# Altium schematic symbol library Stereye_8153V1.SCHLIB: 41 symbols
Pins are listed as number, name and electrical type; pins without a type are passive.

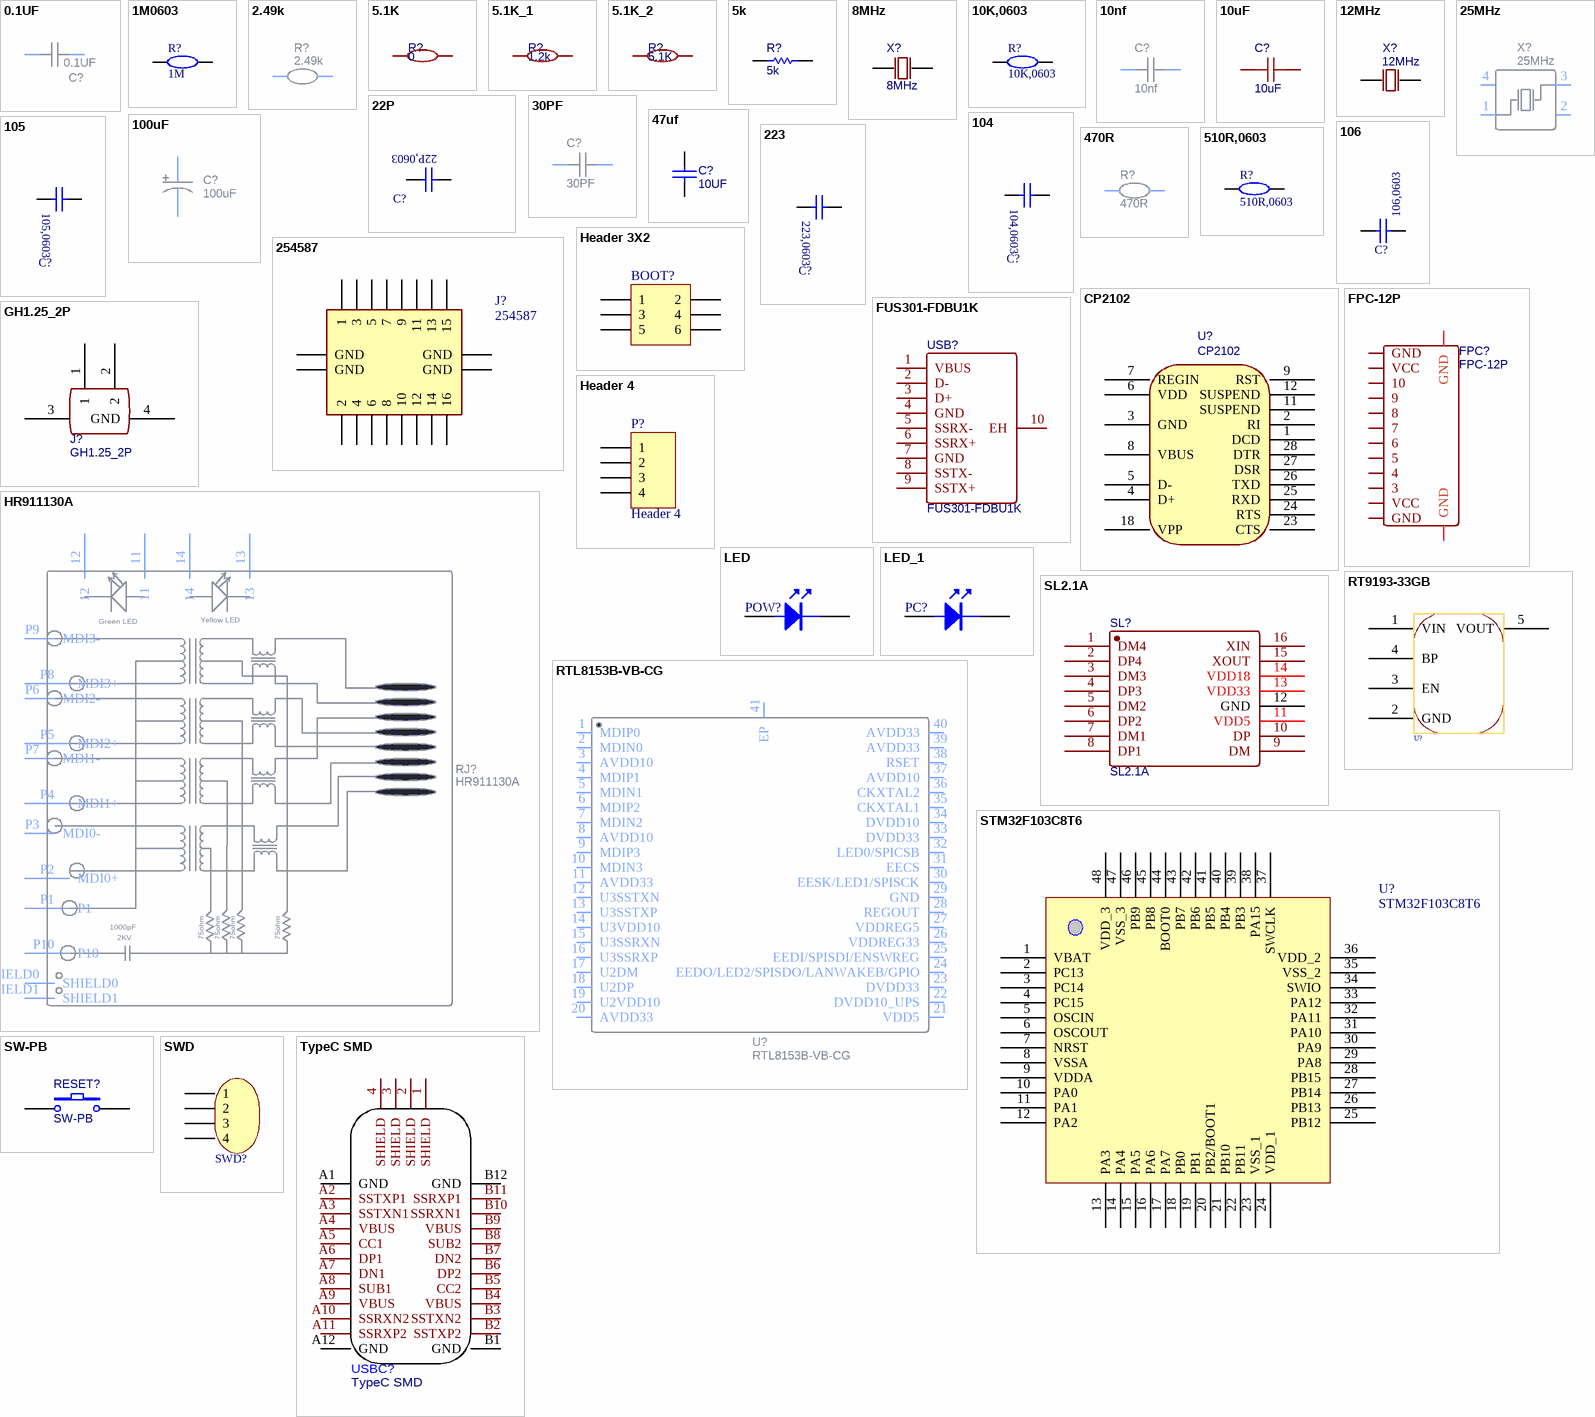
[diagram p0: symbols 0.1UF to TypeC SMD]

## 0.1UF
designator C?
nameAlias: Value(F); Contributor: LCEDA_Lib
footprint C0402_NEW
pins: 1, 2

## 1M0603
designator R?, comment 1M
BOM_Manufacturer: Uniroyal Elec; BOM_Manufacturer Part: 0603WAF1054T5E
footprint 6-0805_N (Chip Resistor, Body 2.0x1.2mm, IPC Medium Density)
pins: 1, 2

## 2.49k
designator R?
nameAlias: Value(Ω); Contributor: LCEDA_Lib
footprint R0603_NEW
pins: 1, 2

## 5.1K
designator R?, comment 0
BOM_Manufacturer: Tyohm; BOM_Manufacturer Part: RMC04025.1K1%N; nameAlias: Resistance (Ohms); Contributor: LCSC
footprint 6-0805_L (Chip Resistor, Body 2.0x1.2mm, IPC High Density)
pins: 1, 2

## 5.1K_1
designator R?, comment 1.2k
BOM_Manufacturer: Tyohm; BOM_Manufacturer Part: RMC04025.1K1%N; nameAlias: Resistance (Ohms); Contributor: LCSC
footprint 6-0805_L (Chip Resistor, Body 2.0x1.2mm, IPC High Density)
pins: 1, 2

## 5.1K_2
designator R?, comment 5.1K
BOM_Manufacturer: Tyohm; BOM_Manufacturer Part: RMC04025.1K1%N; nameAlias: Resistance (Ohms); Contributor: LCSC
footprint 6-0805_L (Chip Resistor, Body 2.0x1.2mm, IPC High Density)
pins: 1, 2

## 5k
designator R?
catid: 20; sourceId: RoYWUgdzx
footprint C0402_NEW
pins: 1, 2

## 8MHz
designator X?
BOM_Manufacturer: ZheJiang East Crystal Elec; BOM_Manufacturer Part: B08000J065; nameAlias: Frequency; Contributor: LCSC
footprint XTAL
pins: 1 OSC1, 2 OSC2

## 10K,0603
designator R?
BOM_Manufacturer: UniOhm; BOM_Manufacturer Part: 060300J0103T5E
footprint C0402_NEW
pins: 1, 2

## 10nf
designator C?
nameAlias: Value(F); Contributor: LCEDA_Lib
footprint C0402_NEW
pins: 1, 2

## 10uF
designator C?
BOM_Manufacturer: SAMSUNG; BOM_Manufacturer Part: CL10A106MP8NNNC; nameAlias: Capacitance
footprint C0402_NEW
pins: 1, 2

## 12MHz
designator X?
BOM_Manufacturer: YXC; BOM_Manufacturer Part: X49SD12MSD2SC; nameAlias: Frequency
footprint XTAL
pins: 1 OSC1, 2 OSC2

## 22P
designator C?  (value not drawn)
BOM_Manufacturer: YAGEO; BOM_Manufacturer Part: CC0603KRX7R9BB104
footprint C0402_NEW
pins: 1, 2

## 25MHz
designator X?
BOM_Manufacturer: Zhejiang Abel Elec; BOM_Manufacturer Part: SMD-3225_4P25MHZ12PF10PPM-40~+85℃; nameAlias: Frequency; Contributor: LCSC; SMT Type: Extend
footprint OSC-SMD_4P-L3.2-W2.5-BL
footprint OSC-SMD_4P-L3.2-W2.5-BL
pins: 1 OSC1, 2 GND, 3 OSC2, 4 GND

## 30PF
designator C?
nameAlias: Value(F); Contributor: LCEDA_Lib
footprint C0402_NEW
pins: 1, 2

## 47uf
designator C?, comment 10UF
catid: 20; sourceId: aYgasJ1jB
footprint C0402_NEW
pins: 1, 2

## 100uF
designator C?
BOM_Manufacturer: SamYoung Electronics; BOM_Manufacturer Part: MVK16VC100M6.3*5_6.3TP; nameAlias: Capacitance; Contributor: LCSC
footprint CAP-SMD_BD6.3-L6.6-W6.6-FD
pins: 1, 2

## 104
designator C?  (value not drawn)
BOM_Manufacturer: YAGEO; BOM_Manufacturer Part: CC0603KRX7R9BB104
footprint C0402_NEW
pins: 1, 2

## 105
designator C?  (value not drawn)
BOM_Manufacturer: YAGEO; BOM_Manufacturer Part: CC0603KRX7R9BB104
footprint C0402_NEW
pins: 1, 2

## 106
designator C?  (value not drawn)
BOM_Manufacturer: YAGEO; BOM_Manufacturer Part: CC0603KRX7R9BB104
footprint C0402_NEW
pins: 1, 2

## 223
designator C?  (value not drawn)
BOM_Manufacturer: YAGEO; BOM_Manufacturer Part: CC0603KRX7R9BB104
footprint C0402_NEW
pins: 1, 2

## 470R
designator R?
nameAlias: Value(Ω); Contributor: LCEDA_Lib
footprint C0402_NEW
pins: 1, 2

## 510R,0603
designator R?
BOM_Manufacturer: UniOhm; BOM_Manufacturer Part: 0603WAJ0511T5E
footprint C0402_NEW
pins: 1, 2

## 254587
designator J?
Connector; Manufacturer_Name: ERNI
footprint MH-16
pins: A1 16, A2 14, A3 12, A4 10, A5 8, A6 6, A7 4, A8 2, B1 15, B2 13, B3 11, B4 9, B5 7, B6 5, B7 3, B8 1, MP1 GND, MP2 GND, MP3 GND, MP4 GND

## CP2102
designator U?
catid: 20; sourceId: 1y8642nlj
footprint QFN28G_0.5-5X5MM
footprint CP2102-28G
pins: 1 DCD, 2 RI, 3 GND, 4 D+, 5 D-, 6 VDD, 7 REGIN, 8 VBUS, 9 RST, 11 SUSPEND, 12 SUSPEND, 18 VPP, 23 CTS, 24 RTS, 25 RXD, 26 TXD, 27 DSR, 28 DTR

## FPC-12P
designator FPC?
BOM_Manufacturer: JUSHUO; BOM_Manufacturer Part: AFC01-S12FCA-00; Contributor: zhqtl2002
footprint FPC-0.5MM-12P
pins: 1 GND, 2 VCC, 3, 4, 5, 6, 7, 8, 9, 10, 11 VCC, 12 GND, 13 GND, 14 GND

## FUS301-FDBU1K
designator USB?
BOM_Manufacturer: TXGA; Contributor: LCSC
footprint USB3.0-A-TH_FUS301-FDBU1K
pins: 1 VBUS, 2 D-, 3 D+, 4 GND, 5 SSRX-, 6 SSRX+, 7 GND, 8 SSTX-, 9 SSTX+, 10 EH

## GH1.25_2P
designator J?
Contributor: AKER
footprint GH1.25_2P
pins: 1, 2, 3, 4 GND

## Header 3X2
designator BOOT?  (value not drawn)
Header, 3-Pin, Dual row
signal-integrity model Connector
footprint HDR2X3 (Connector; Header; 3x2 Position)
pins: 1, 2, 3, 4, 5, 6

## Header 4
designator P?
Header, 4-Pin
footprint HDR1X4 (Connector; Header; 4 Position)
signal-integrity model Connector
pins: 1, 2, 3, 4

## HR911130A
designator RJ?
BOM_Manufacturer: HANRUN
footprint RJ45-TH_HR911130A
pins: 11, 12, 13, 14, P1, P2 MDI0+, P3 MDI0-, P4 MDI1+, P5 MDI2+, P6 MDI2-, P7 MDI1-, P8 MDI3+, P9 MDI3-, P10, SHIELD0, SHIELD1

## LED
designator POW?, comment LEDred  (value not drawn)
footprint LED; pin to pad A>1 K>2
pins: A 1, K 2

## LED_1
designator PC?, comment LEDgreen  (value not drawn)
footprint LED; pin to pad A>1 K>2
pins: A 1, K 2

## RT9193-33GB
designator U?  (value not drawn)
ICA_MFR_NAME: RICHTEK; ICA_PARTNUM: $$2191094$$RT9193-15CU5; Part Number: TMP-13
footprint SOT-23-5
pins: 1 VIN, 2 GND, 3 EN, 4 BP, 5 VOUT

## RTL8153B-VB-CG
designator U?
BOM_Manufacturer: REALTEK(瑞昱); Contributor: LCSC
footprint QFN-40_L5.0-W5.0-P0.40-BL-EP3.7
pins: 1 MDIP0, 2 MDIN0, 3 AVDD10, 4 MDIP1, 5 MDIN1, 6 MDIP2, 7 MDIN2, 8 AVDD10, 9 MDIP3, 10 MDIN3, 11 AVDD33, 12 U3SSTXN, 13 U3SSTXP, 14 U3VDD10, 15 U3SSRXN, 16 U3SSRXP, 17 U2DM, 18 U2DP, 19 U2VDD10, 20 AVDD33, 21 VDD5, 22 DVDD10_UPS, 23 DVDD33, 24 EEDO/LED2/SPISDO/LANWAKEB/GPIO, 25 EEDI/SPISDI/ENSWREG, 26 VDDREG33, 27 VDDREG5, 28 REGOUT, 29 GND, 30 EESK/LED1/SPISCK, 31 EECS, 32 LED0/SPICSB, 33 DVDD33, 34 DVDD10, 35 CKXTAL1, 36 CKXTAL2, 37 AVDD10, 38 RSET, 39 AVDD33, 40 AVDD33, 41 EP

## SL2.1A
designator SL?
BOM_Manufacturer: CoreChips; Contributor: LCSC; SMT Type: Extend
footprint SOP-16_L10.0-W3.9-P1.27-LS6.0-BL
pins: 1 DM4, 2 DP4, 3 DM3, 4 DP3, 5 DM2, 6 DP2, 7 DM1, 8 DP1, 9 DM, 10 DP, 11 VDD5, 12 GND, 13 VDD33, 14 VDD18, 15 XOUT, 16 XIN

## STM32F103C8T6
designator U?
footprint STM32-48P
pins: 1 VBAT, 2 PC13, 3 PC14, 4 PC15, 5 OSCIN, 6 OSCOUT, 7 NRST, 8 VSSA, 9 VDDA, 10 PA0, 11 PA1, 12 PA2, 13 PA3, 14 PA4, 15 PA5, 16 PA6, 17 PA7, 18 PB0, 19 PB1, 20 PB2/BOOT1, 21 PB10, 22 PB11, 23 VSS_1, 24 VDD_1, 25 PB12, 26 PB13, 27 PB14, 28 PB15, 29 PA8, 30 PA9, 31 PA10, 32 PA11, 33 PA12, 34 SWIO, 35 VSS_2, 36 VDD_2, 37 SWCLK, 38 PA15, 39 PB3, 40 PB4, 41 PB5, 42 PB6, 43 PB7, 44 BOOT0, 45 PB8, 46 PB9, 47 VSS_3, 48 VDD_3

## SW-PB
designator RESET?
Contributor: liujiayu6388
footprint 贴片按键（红头）
footprint Key
pins: 1, 2

## SWD
designator SWD?  (value not drawn)
BOM_Manufacturer: Ckmtw; BOM_Manufacturer Part: 210S-1*4P L=11.6MMGold-plated black
footprint HDR1X4H (Connector; Header; 4 Position; Right Angle)
pins: 1, 2, 3, 4

## TypeC SMD
designator USBC?
footprint USB-C-SMD_MC-312D-C
pins: 1 SHIELD, 2 SHIELD, 3 SHIELD, 4 SHIELD, A1 GND, A2 SSTXP1, A3 SSTXN1, A4 VBUS, A5 CC1, A6 DP1, A7 DN1, A8 SUB1, A9 VBUS, A10 SSRXN2, A11 SSRXP2, A12 GND, B1 GND, B2 SSTXP2, B3 SSTXN2, B4 VBUS, B5 CC2, B6 DP2, B7 DN2, B8 SUB2, B9 VBUS, B10 SSRXN1, B11 SSRXP1, B12 GND

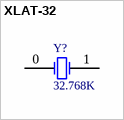
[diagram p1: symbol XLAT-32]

## XLAT-32
designator Y?, comment 32.768K
BOM_Manufacturer: KDS; BOM_Manufacturer Part: DST310S 32.768KHz
footprint PCBComponent_1
footprint XLAT-32
pins: 0 OSC1, 1 OSC2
